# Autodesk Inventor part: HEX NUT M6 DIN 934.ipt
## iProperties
Created: 2006-02
Part Number: HEX NUT M6 DIN 934.ipt
Material: Steel, Mild
Description: Hex Nut
Document SubType Name: Modeling
Standard: DIN 934
Designer: Andy Moles
Standards Organization: DIN
Language: en-US
Size Designation: M6
Categories: <MemberInstance><Categories><Category DisplayName="Fasteners" InternalName="e4da775c-781d-43d5-af7c-5136215cf5a6" Mnemonic="FSTN"><Category DisplayName="Nuts" I
Density: 7.86 g/cm^3
Mass: 2.52494 g
Surface Area: 3.5226 cm^2
Volume: 0.321239 cm^3
Author: Andy Moles
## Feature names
1. Body [Extrusion]
2. Chamfer1 [Revolution]
3. Thread [Hole]
4. Chamfer2
5. Chamfer3
